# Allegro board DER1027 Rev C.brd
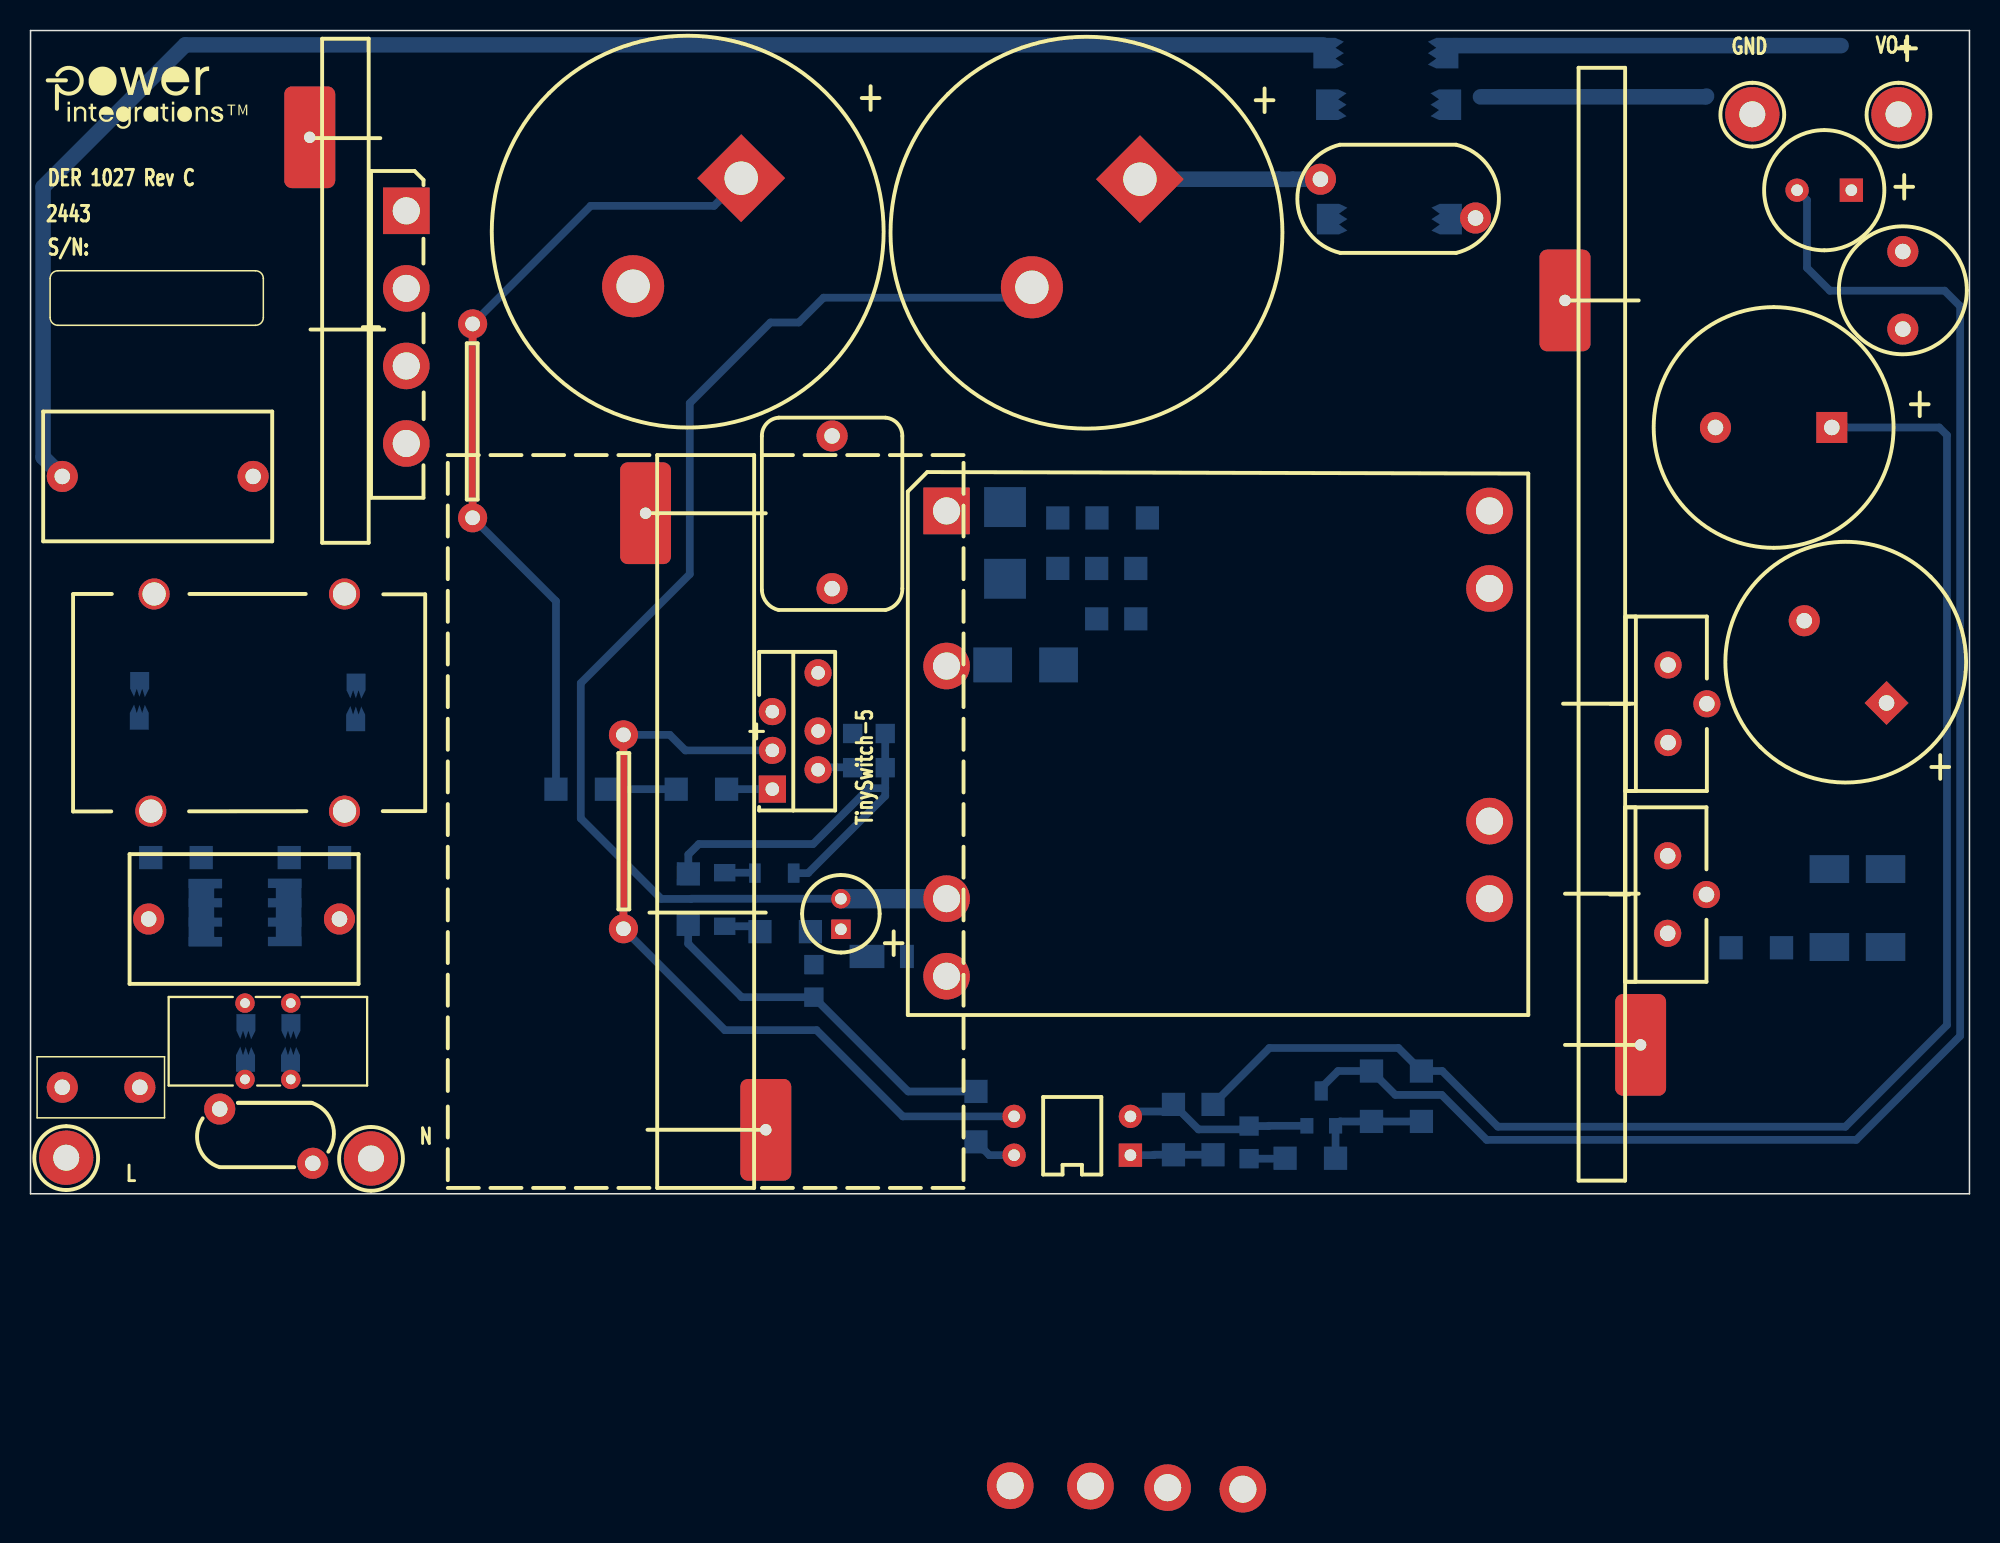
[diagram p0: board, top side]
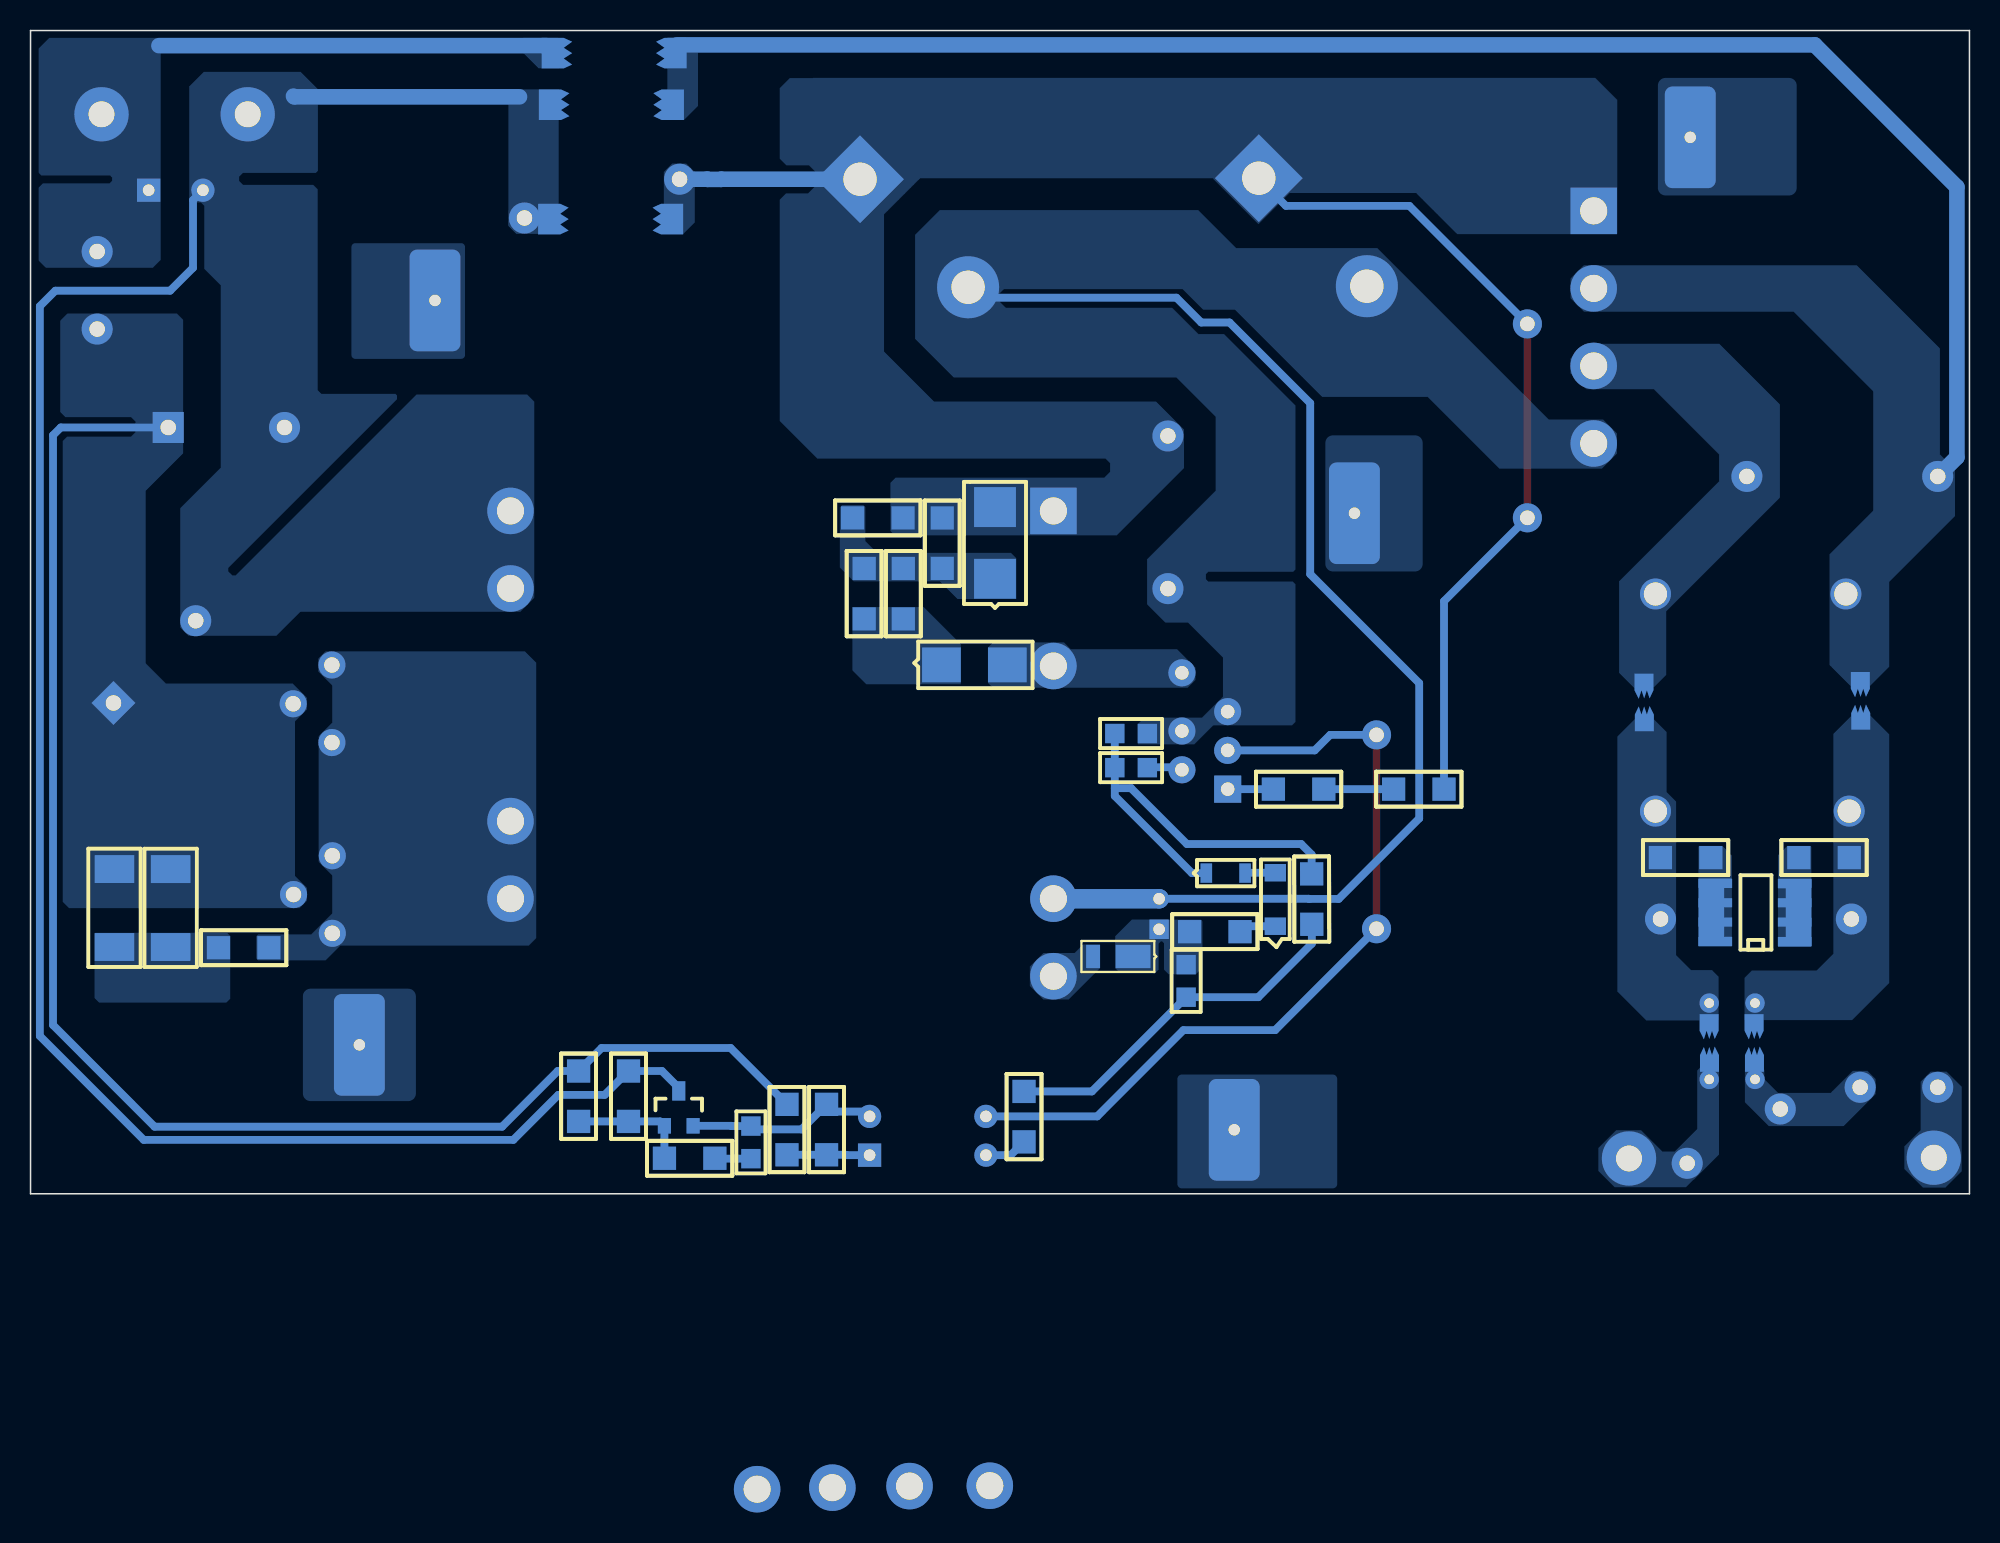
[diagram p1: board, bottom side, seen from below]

Outline 127 x 76.2 mm; copper layers: TOP, BOTTOM. Coordinates in mm from the lower left corner of the outline.
Outline path: 0,76.2 127,76.2 127,0 0,0 0,76.2

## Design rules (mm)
constraint set DEFAULT: min track width 0.508

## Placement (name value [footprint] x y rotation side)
BR1  GBU8K-BP  [PIDAXBRIDGEGBU8]  24.61 64.39 270 top
C1  330 nF  [PINP_XCAPRAD15X8P5X14HD040]  20.24 18 180 top
C2  270 uF  [PIPOLCAPCLYD985LS394086]  46.57 66.51 225 top
C3  1 uF  [PINPCAPRAD_12P6X9P2_LS10_D40]  52.5 49.64 270 top
C4  0.47 uF  [PISMC0805]  55.98 30.15 180 bottom
C5  1000 pF  [PISMC1206]  67.28 44.27 270 bottom
C7  47 uF  [PIPOLCAPCLYD200LS80030]  53.08 17.33 90 top
C8  470 pF  [PISMC1206]  111.39 16.12 0 bottom
C9  1800 uF  [PIPOLCAPCLYD630LS300040]  121.57 32.15 135 top
C10  1800 uF  [PIPOLCAPCLYD630LS300040]  117.98 50.2 180 top
C12  22 nF  [PISMC0805]  79.81 4.43 270 bottom
C14  150 uF  [PIPOLCAPCLYD320LS140030]  119.26 65.74 180 top
C15  330 nF  [PINP_XCAPRAD15X8P5X14HD040]  14.58 46.99 180 top
C16  270 uF  [PIPOLCAPCLYD985LS394086]  72.68 66.44 225 top
CY1  2.2 nF  [PINPYCAPRAD540X290LS400040]  84.49 66.46 0 top
D1  BAV21WS-7-F  [PISMSOD323]  49.99 21.01 180 bottom
D2  RS2MA-13-F  [PISMDO214AC12]  67.34 34.65 180 bottom
D3  DFLR1200-7  [PISMDDFLR120012]  54.76 15.54 180 bottom
D4  V20202C-M3/4W  [PIDVTO2203VF1]  107.26 32.1 90 top
D6  V20202C-M3/4W  [PIDVTO2203VF1]  107.23 19.6 90 top
D7  BZT52-C10J  [PI_SM_SOD-123_12]  45.47 17.53 90 bottom
F1  5 A  [PI_RST_MICROFUSE]  2.08 6.97 0 top
HS1  HEATSINK  DRW Custom TOP-JX IC DER-1026  [PI_HS_2P_DER-1026_TOP-JX_IC]  41.05 48.39 270 top
HS2  HEATSINK DRW Custom Diode Bridge DER1027  [PIHSDER1027DB]  22.15 42.64 90 top
HS3  HEATSINK DRW Custom SECDIODE DER-1027  [PI_HS_2P_DER-1027_SECDIODE]  104.44 0.86 90 top
JP1  J  [PI_JUMPER500]  28.96 44.28 90 top
JP2  J  [PI_JUMPER500]  38.84 30.06 270 top
L1  250 uH  [PI_TOROID_CMC13X6_5P8P_V]  15.55 9.99 0 top
L2  10 mH  [PI_TOROID_BALUN_1]  7.87 39.29 270 top
L3  1.5 uH  [PI_CHOKE_TOKO]  122.64 56.64 90 top
L4  80 ohm  [PISMR0805]  55.98 27.91 180 bottom
NOREF  -  []  0 76.2 0 top
NOREF#2  -  []  -228.6 -144.78 0 top
NOREF#3  -  []  57.66 -90.3 0 top
NOREF#4  -  []  1.02 74.32 0 top
NOREF#5  -  []  0 0 90 top
R1  1 M  [PISMR1206]  7.87 22.02 0 bottom
R2  1 M  [PISMR1206]  16.94 22.02 0 bottom
R5  6.34 k  [PISMR0805]  51.31 15.01 270 bottom
R7  4.02M  [PISMR1206]  34.42 26.5 0 bottom
R8  4.02M  [PISMR1206]  42.29 26.5 0 bottom
R12  47  [PISMR1206]  51.08 17.17 180 bottom
R13  20  [PISMR2010]  117.82 21.27 270 bottom
R15  2 k  [PISMR1206]  74.86 2.56 90 bottom
R16  1.0 k  [PISMR1206]  77.45 5.86 270 bottom
R17  20.0 k  [PISMR1206]  85.48 2.33 180 bottom
R18  191 k  [PISMR1206]  91.1 8.04 270 bottom
R19  10 k  [PISMR1206]  87.83 4.74 90 bottom
R21  20  [PISMR1206]  72.4 40.96 270 bottom
R22  20  [PISMR1206]  69.83 40.96 270 bottom
R23  0  [PISMR1206]  43.08 17.65 89.9 bottom
R24  0  [PISMR1206]  61.93 6.7 270 bottom
R25  1.00 M  [PISMR1206]  69.85 44.27 0 bottom
R26  20  [PISMR2010]  121.5 21.27 270 bottom
RV1  275 Vac  [PIDISC350X160LS210X140040]  12.39 5.55 0 top
SG1  5.5mm gap  [PI_SPARK_GAP_5P5MM]  89 63.85 0 bottom
SG2  5.5mm gap  [PI_SPARK_GAP_5P5MM]  88.95 71.34 0 bottom
SG3  5.5mm gap  [PI_SPARK_GAP_5P5MM]  88.78 74.72 0 bottom
T1  PQ35/35  [PI_BOBBIN_BPQ35_35_12P]  60 44.73 0 top
TP1  L (BLK)  [PITPKEYSTONE125X125]  2.34 2.36 0 top
TP2  N (WHT)  [PITPKEYSTONE125X125]  22.3 2.31 0 top
TP3  VO+ (RED)  [PITPKEYSTONE125X125]  122.35 70.71 0 top
TP4  GND (BLK)  [PITPKEYSTONE125X125]  112.78 70.71 0 top
U1  CAP200DG  [PI_IC_SMD_SO8_CAPZERO]  11.45 16.53 90 bottom
U2  TNY5077E  [PIICESIP76TH]  48.59 26.5 90 top
U3  LTV817D  [PI_DIP4]  72.04 2.53 90 top
U4  LMV431AIMF  [PISMSOT23132]  83.6 4.45 180 bottom
VR2  SMBJ170A  [PISMDO214AA12]  63.83 40.28 90 bottom

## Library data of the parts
BR1 = DISCRETE BRIDGE_+~~-: alternate symbols: (pidaxbridgegbu8_horz)
C1 C15 = CAP NP: alternate symbols: (pinp_xcaprad15x8p5x14Hd040H); room: 1
C2 C16 = CAP POL
C3 = CAP NP: alternate symbols: (pinpcaprad_12p6x9p2_ls10_d400H)
C4 C12 = CAP NP: alternate symbols: (Unisem_RMCF0805UL)
C5 = CAP NP: tolerance: 10
C7 = CAP POL: alternate symbols: (pipolcapclyd200ls80030h); tolerance: 20
C8 = CAP NP: alternate symbols: (pismc1206_1); tolerance: 10
C9 C10 = CAP POL: alternate symbols: (pipolcapclyd630ls3000401000h)
C14 = CAP POL: alternate symbols: (pipolcapclyd320ls140030430h); tolerance: 20
CY1 = CAP NP
D1 = DIODE: alternate symbols: (SOD323_UL_IPC,pismsod323_1)
D2 D3 = DIODE
D4 D6 = DS_DUAL_CK_AKA: alternate symbols: (pidvto2203,pidvto2203h)
D7 = ZENER_DIODE
F1 = FUSE: alternate symbols: (pirstmicrofusehoz); room: 1
HS1 = hs_2P_DER-1026_TOP-JXIC
HS2 = hs_1P_DER1027DB
HS3 = hs_2P_DER-1027_SECDIODE
JP1 JP2 = JUMPER_2
L1 = TORRID 4P_12_34: room: 1
L2 = TORRID 4P_12_34
L3 = INDUCTOR: alternate symbols: (pi_choke_toko_h); tolerance: 0.2
L4 = INDUCTOR_BEAD_2
R1 R2 R12 R13 R15-R19 R21-R26 = R
R5 = R: alternate symbols: (Unisem_RMCF0805UL)
R7 R8 = R: alternate symbols: (pismr1206_1)
RV1 = VARISTOR: alternate symbols: (pi_disc_354x220_ls220x10_040_h); room: 1
SG1-SG3 = SPARK_GAP
T1 = BPQ35/35_12P/GENERIC
TP1-TP4 = TESTPOINT
U1 = CAPZero: room: 1
U2 = TinySwitch-5E
U3 = OPTO_A_B
U4 = TL431/SOT-23_RCA
VR2 = DIODE_ZENER

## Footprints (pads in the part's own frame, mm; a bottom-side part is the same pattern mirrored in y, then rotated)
PI_BOBBIN_BPQ35_35_12P
  rect 3.048x3.048 hole 1.778: 1(0,0)
  round 3.048 hole 1.778: 2(19.406,-64.084) 3(0,-10.16) 4(4.166,-63.856) 5(0,-25.4) 6(0,-30.48) 7(9.423,-63.881) 8(35.56,-25.4) 9(35.56,-20.32) 10(14.478,-63.983) 11(35.56,-5.08) 12(35.56,0)
PI_CHOKE_TOKO
  round 2.032 hole 1.016: 1(0,0) 2(5.08,0)
PI_DIP4
  rect 1.524x1.524 hole 0.762: 1(0,0)
  round 1.524 hole 0.762: 2(2.54,0) 3(2.54,7.62) 4(0,7.62)
PI_HS_2P_DER-1026_TOP-JX_IC
  rrect 6.66x3.333 hole 0.75: 1(3.81,-0.762) 2(44.199,7.112)
PI_HS_2P_DER-1027_SECDIODE
  rrect 6.66x3.333 hole 0.75: 1(8.893,-1.016) 2(57.658,3.937)
PI_IC_SMD_SO8_CAPZERO
  rect 0.599x2.2 smd: 1(0,0) 2(1.27,0) 3(2.54,0) 4(3.81,0) 5(3.81,5.199) 6(2.54,5.199) 7(1.27,5.199) 8(0,5.199)
PI_JUMPER500
  round 1.905 hole 0.965: 1(0,0) 2(12.7,0)
PI_RST_MICROFUSE
  round 2.032 hole 1.016: 1(0,0) 2(5.08,0)
PI_SM_SOD-123_12
  rect 1.143x1.397 smd: 1(0,0) 2(3.505,0)
PI_SPARK_GAP_5P5MM
  custom 0.5x0.5 smd: 1(-3.75,0) 2(3.75,0)
PI_TOROID_BALUN_1
  round 2.032 hole 1.524: 1(14.224,0.013) 2(0,0.229) 3(14.224,12.7) 4(0,12.7)
PI_TOROID_CMC13X6_5P8P_V
  round 1.27 hole 0.635: 1(1.5,-2.5) 2(1.5,2.5) 3(-1.5,-2.5) 4(-1.5,2.5)
PIDAXBRIDGEGBU8
  rect 3.048x3.048 hole 1.778: 1(0,0)
  round 3.048 hole 1.778: 2(5.08,0) 3(10.16,0) 4(15.24,0)
PIDISC350X160LS210X140040
  round 2.032 hole 1.016: 1(0,0) 2(6.096,-3.556)
PIDVTO2203VF1
  round 1.778 hole 1.016: 1(-2.54,0) 2(0,-2.54) 3(2.54,0)
PIHSDER1027DB
  rrect 6.66x3.333 hole 0.75: 1(26.561,3.861)
PIICESIP76TH
  rect 1.778x1.778 hole 0.889: 1(0,0)
  round 1.778 hole 0.889: 2(1.27,-2.997) 3(2.54,0) 4(3.81,-2.997) 5(5.08,0) 7(7.62,-2.997)
PINP_XCAPRAD15X8P5X14HD040
  round 2.032 hole 1.016: 1(0,0) 2(12.499,0)
PINPCAPRAD_12P6X9P2_LS10_D40
  round 2.032 hole 1.016: 1(0,0) 2(10,0)
PINPYCAPRAD540X290LS400040
  round 2.032 hole 1.016: 1(0,0) 2(10.16,-2.54)
PIPOLCAPCLYD200LS80030
  rect 1.27x1.27 hole 0.762: 1(0,0)
  round 1.27 hole 0.762: 2(2,0)
PIPOLCAPCLYD320LS140030
  rect 1.524x1.524 hole 0.762: 1(0,0)
  round 1.524 hole 0.762: 2(3.556,0)
PIPOLCAPCLYD630LS300040
  rect 2.032x2.032 hole 1.016: 1(0,0)
  round 2.032 hole 1.016: 2(7.62,0)
PIPOLCAPCLYD985LS394086
  rect 4.064x4.064 hole 2.184: 1(0,-0.025)
  round 4.064 hole 2.184: 2(10.008,-0.025)
PISMC0805
  rect 1.27x1.27 smd: 1(0,0) 2(2.134,0)
PISMC1206
  rect 1.524x1.524 smd: 1(0,0) 2(3.302,0)
PISMDDFLR120012
  rect 2.286x1.524 smd: 1(-0.025,0)
  rect 0.914x1.524 smd: 2(-2.642,0)
PISMDO214AA12
  rect 2.616x2.743 smd: 1(0,0) 2(4.699,0)
PISMDO214AC12
  rect 2.54x2.286 smd: 1(0,0) 2(4.318,0)
PISMR0805
  rect 1.27x1.27 smd: 1(0,0) 2(2.134,0)
PISMR1206
  rect 1.524x1.524 smd: 1(0,0) 2(3.302,0)
PISMR2010
  rect 1.829x2.591 smd: 1(0,0) 2(5.105,0)
PISMSOD323
  rect 0.762x1.27 smd: 1(0,0) 2(2.54,0)
PISMSOT23132
  rect 0.864x1.016 smd: 1(-1.88,0) 2(0,0)
  rect 0.864x1.27 smd: 3(-0.94,2.286)
PITPKEYSTONE125X125
  round 3.556 hole 1.702: 1(0,0)

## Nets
BR: BR1.2 C15.2 L2.2 SG2.1 SG3.1
N1180530: C9.2 C10.2 C14.2 CY1.2 R19.2 SG1.2 SG2.2 T1.11 T1.12 TP4.1 U4.3
N1180572: C8.1 D4.1 D4.3 D6.1 D6.3 T1.8 T1.9
N1180580: C8.2 R13.2 R26.2
N1180772: C9.1 C10.1 D4.2(CATHODE) D6.2(CATHODE) L3.1 R13.1 R16.1 R18.1 R26.1
N1180800: C14.1 L3.2 SG3.2 TP3.1
N1180998: BR1.4 C2.2 C3.2 C4.2 C7.2 C16.2 T1.5 U2.4 U2.5
N1181144: R7.2 R8.1
N1181148: D2.2 T1.3 U2.7
N1181266: C7.1 D3.1 R5.1 R12.1
N1181270: R15.1 R16.2 U3.1
N1181336: R17.1 R18.2 R19.1 U4.1(VREF)
N1181354: R8.2 U2.1
N1181442: C12.1 R15.2 U3.2 U4.2
N1193924: D1.2 D7.2
N1193928: D7.1(CATHODE) R12.2
N11509583: C1.2 L1.4 L2.1 R1.1
N11509663: R1.2 U1.1 U1.2 U1.3 U1.4
N11509667: R2.1 U1.5 U1.6 U1.7 U1.8(NC8)
N11509705: C1.1 L1.2 L2.3 R2.2
N11509765: F1.2 L1.3 RV1.1
N11509809: L1.1 RV1.2 TP2.1
N11514098: C12.2 R17.2
N11558446: BR1.3(AC2) C15.1 L2.4
N11565135: C5.2 R21.1 R22.1 R25.2 VR2.1
N11566250: F1.1 TP1.1
N11596495: D2.1 R21.2 R22.2
N11618490: D3.2 T1.6
N12576026: C4.1 D1.1 L4.1 R23.2
N12603395: BR1.1 C2.1 C3.1 C5.1 C16.1 CY1.1 JP1.1 JP1.2 R7.1 R25.1 SG1.1 T1.1 VR2.2
N12603576: JP2.1 JP2.2 U2.3 U3.3(E)
N12614295: R5.2 R23.1 R24.1
N12614386: R24.2 U3.4
N12619931: HS1.2
N12619939: HS1.1
N12620029: HS2.1
N12620119: HS3.2
N12620127: HS3.1
N12646059: L4.2 U2.2

Pads without a net: T1 2 4 7 10

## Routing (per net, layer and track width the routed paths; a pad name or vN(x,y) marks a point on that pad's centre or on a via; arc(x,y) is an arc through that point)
BR: length 107.2
  BOTTOM w1.016: 84.67,75.26 10.13,75.26 0.82,65.95 0.82,48.25 C15.2
N1180530: length 126.3
  BOTTOM w0.508: C14.2 116.36,65.09 116.36,60.66 117.86,59.16 125.37,59.16 126.39,58.14 126.39,10.34 119.58,3.53 95.38,3.53 92.43,6.48 89.4,6.48 R19.2 85.64,8.04 84.54,6.94 U4.3
  BOTTOM w1.016: 94.97,71.86 109.73,71.86 109.78,71.91
N1180772: length 100.9
  BOTTOM w0.508: C10.1 125.02,50.2 125.53,49.69 125.53,11.05 118.87,4.39 96.11,4.39 92.47,8.04 R18.1 89.59,9.55 81.15,9.55 R16.1
N1180800: length 25.4
  BOTTOM w1.016: 93.18,75.21 118.59,75.21
N1180998: length 83.1
  BOTTOM w0.508: C7.2 43.27,19.33 43.26,19.31 41.32,19.31 36.04,24.59 36.04,33.45 43.18,40.59 43.18,51.79 48.46,57.07 50.32,57.07 51.94,58.7 64.55,58.7 64.73,58.52 C16.2 64.83,58.62
  BOTTOM w1.27: C7.2 60,19.33 T1.5
N1181144: length 4.6
  BOTTOM w0.508: R7.2 R8.1
N1181270: length 5.4
  BOTTOM w0.508: R16.2 R15.1 73.59,2.56 73.57,2.53 U3.1
N1181336: length 7.9
  BOTTOM w0.508: R18.2 R19.1 85.77,4.74 U4.1 85.48,2.33 R17.1
N1181354: length 3
  BOTTOM w0.508: R8.2 U2.1
N1181442: length 12.7
  BOTTOM w0.508: U3.2 72.36,5.38 74.39,5.38 R15.2 76.5,4.22 79.6,4.22 C12.1 81.08,4.43 81.1,4.45 U4.2
N1193924: length 2
  BOTTOM w0.508: D1.2 47.42,21.03 D7.2
N1193928: length 2.5
  BOTTOM w0.508: R12.2 47.42,17.53 D7.1
N11514098: length 2.4
  BOTTOM w0.508: R17.2 82.15,2.3 C12.2
N12576026: length 28.1
  BOTTOM w0.508: D1.1 50.93,21.01 55.98,26.06 55.98,26.57 ; 55.98,26.57 L4.1 C4.1 ; 55.98,26.57 54.91,26.57 51.26,22.91 43.77,22.91 43.09,22.23 43.09,20.95
N12603395: length 66.1
  TOP w0.508: JP1.2 JP1.1
  BOTTOM w0.508: JP1.2 36.69,64.71 44.77,64.71 46.57,66.51 ; JP1.1 34.42,38.82 R7.1
  BOTTOM w1.016: CY1.1 82.67,66.46 82.66,66.45 81.77,66.45 81.76,66.46 C16.1
N12603576: length 53.5
  TOP w0.508: JP2.1 JP2.2
  BOTTOM w0.508: U3.3 57.13,5.07 51.49,10.72 45.48,10.72 JP2.2 ; U2.3 42.89,29.04 41.87,30.06 JP2.1
N12614295: length 24.1
  BOTTOM w0.508: R23.1 43.08,16.38 46.58,12.88 R5.2 57.48,6.7 R24.1
N12614386: length 2.9
  BOTTOM w0.508: U3.4 62.8,2.53 R24.2
N12646059: length 2.3
  BOTTOM w0.508: U2.2 51.75,27.94 53.82,27.94 L4.2

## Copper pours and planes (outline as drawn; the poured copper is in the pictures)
BR on BOTTOM (solid shape): 7.77,33.09 7.49,32.53 7.31,33.09 7.13,32.55 6.96,33.09 6.78,32.55 6.53,33.09 6.53,34.18 7.77,34.18
BR on BOTTOM: 84.19,70.35 85.29,70.35 85.29,75.75 83.85,75.75 83.28,75.18 83.28,71.26
BR on BOTTOM: 9.17,41.88 6.31,44.75 6.31,52.57 11.52,57.78 25.25,57.78 26.13,58.66 26.13,59.95 25.26,60.82 7.39,60.82 1.94,55.38 1.94,48.44 0.95,47.45 0.95,44.39 5.26,40.08 5.26,34.52 6.55,33.22 7.75,33.22 9.17,34.65
N1180530 on BOTTOM: 92.91,64.89 92.74,64.72 92.74,62.97 92.82,62.89 95.17,62.89 95.71,63.42 95.71,63.7 95.7,63.71 95.7,64.4 95.2,64.89
N1180530 on BOTTOM: 92.41,72.35 92.41,62.89 95.18,62.89 95.7,63.41 95.7,71.85 95.21,72.35
N1180530 on BOTTOM: 109.32,38.12 110.9,36.55 116.65,36.55 117.2,37.09 117.2,44.91 114.54,47.56 114.54,59.51 115.62,60.59 115.62,64.72 115.84,64.94 116.5,64.94 116.61,65.05 116.61,72.56 116.58,72.56 115.65,73.49 109.31,73.49 108.18,72.36 108.18,67.01 108.31,66.88 113.1,66.88 113.1,66.86 113.34,66.62 113.34,66.35 113.08,66.09 108.48,66.09 108.19,65.8 108.19,52.64 107.95,52.4 103.1,52.4 103,52.3 103,52.04 114.05,40.99 114.05,40.77 113.91,40.63 113.78,40.51 113.56,40.51 101.71,52.36 94.48,52.36 94.01,51.89 94.01,39.12 94.01,39.11 94.01,39.04 94.92,38.12
N1180572 on BOTTOM: 107.24,18.36 107.24,20.85 108.13,21.74 108.13,29.98 107.24,30.86 107.24,33.3 108.15,34.21 108.15,35.05 107.67,35.53 94.62,35.53 93.88,34.79 93.88,16.74 94.37,16.26 106.71,16.26 107.67,15.29 112.09,15.29 112.22,15.42 112.22,16.87 112.09,16.99 108.61,16.99
N1180580 on BOTTOM: 122.81,17.04 122.81,12.83 122.5,12.52 114.17,12.52 113.92,12.78 113.92,16.89 114.12,17.09 122.76,17.09
N1180772 on BOTTOM: 109.68,30.95 108.89,31.73 108.89,32.49 109.83,33.43 118.14,33.43 119.46,34.75 119.46,46.05 117.01,48.5 117.01,57.26 117.41,57.67 124.58,57.67 125.06,57.19 125.06,51.22 124.71,50.88 120.42,50.88 120.13,50.58 120.13,49.89 120.42,49.6 124.6,49.6 124.89,49.31 124.89,19.13 124.48,18.71 109.38,18.71 108.89,19.2 108.89,20.03 109.68,20.82
N1180800 on BOTTOM: 126.47,75.03 126.47,66.88 126.29,66.7 121.79,66.7 121.66,66.57 121.66,66.36 121.82,66.19 126.19,66.19 126.47,65.91 126.47,61.13 125.99,60.66 118.99,60.66 118.47,61.17 118.47,75.57 118.62,75.72 125.77,75.72
N1180800 on BOTTOM: 92.43,75.73 92.43,73.73 93.72,73.73 94.7,74.71 94.7,75.73 94.7,75.73 92.43,75.73
N1180998 on BOTTOM: 44.37,30.68 44.15,30.91 44.15,39.93 44.32,40.11 49.86,40.11 50.01,40.26 50.01,40.59 49.86,40.74 44.3,40.74 44.15,40.89 44.15,51.64 48.82,56.31 50.5,56.31 52.22,58.04 63.12,58.04 63.55,58.47 63.55,58.95 63.25,59.26 51.54,59.26 50.19,57.91 48.11,57.91 42.39,52.2 35.48,52.2 30.78,47.5 24.08,47.5 23.09,48.49 23.09,49.81 24,50.72 27.56,50.72 38.79,61.95 48.03,61.95 50.52,64.44 67.44,64.44 69.06,62.81 69.06,56.01 66.52,53.47 51.94,53.47 49.38,50.9 49.38,46.05 53.88,41.55 53.87,41.53 53.87,38.61 52.67,37.41 51.18,37.41 48.9,35.13 48.9,32.56 50.27,31.19 54.05,31.19 54.47,30.77 54.47,29.44 50.77,29.44 49.53,30.68
N1181148 on BOTTOM: 51.21,33.15 63.97,33.15 64.29,33.46 64.29,35.79 63.96,36.12 59.31,36.12 58.86,35.67 51.9,35.67 50.7,34.47 50.7,33.66
N1181266 on BOTTOM: 53.67,17.96 53.68,17.97 54.86,17.97 55.96,16.87 55.96,14.78 55.7,14.53 53.26,14.53 53.11,14.68 53.11,16.38 52.96,16.54 52.88,16.54 52.76,16.41 52.76,14.68 52.45,14.38 50.67,14.38 50.24,14.81 50.24,17.86 50.34,17.96
N11509583 on BOTTOM (solid shape): 6.96,31.49 7.13,32.03 7.31,31.49 7.49,32.03 7.74,31.49 7.74,30.4 6.5,30.4 6.5,31.49 6.78,32.05
N11509583 on BOTTOM (solid shape): 14.73,10.68 14.45,10.12 14.27,10.68 14.09,10.14 13.92,10.68 13.74,10.14 13.48,10.68 13.48,11.77 14.73,11.77
N11509583 on BOTTOM: 14.73,11.38 14.73,14.15 14.25,14.63 10.01,14.63 8.92,15.72 8.92,30.12 7.72,31.32 6.48,31.32 5.26,30.1 5.26,13.8 7.68,11.38
N11509663 on BOTTOM (solid shape): 12.54,20.01 12.03,20.01 12.03,16.8 12.54,16.8 12.54,16.2 10.36,16.2 10.36,20.61 12.54,20.61
N11509663 on BOTTOM: 10.36,16.22 12.54,16.22 12.54,22.18 11.94,22.78 10.41,22.78 10.36,22.73
N11509667 on BOTTOM (solid shape): 17.75,16.22 15.56,16.22 15.56,16.83 16.07,16.83 16.07,20.03 15.56,20.03 15.56,20.64 17.75,20.64
N11509667 on BOTTOM: 17.75,17.57 17.75,17.57 17.75,16.22 15.56,16.22 15.56,22.17 16.18,22.78 17.7,22.78 17.75,22.73
N11509705 on BOTTOM (solid shape): 17.68,10.68 17.4,10.12 17.22,10.68 17.04,10.14 16.86,10.68 16.69,10.14 16.43,10.68 16.43,11.77 17.68,11.77
N11509705 on BOTTOM (solid shape): 21.13,31.39 21.31,31.93 21.49,31.39 21.66,31.93 21.92,31.39 21.92,30.3 20.67,30.3 20.67,31.39 20.95,31.95
N11509705 on BOTTOM: 16.43,11.35 16.43,14.22 16.87,14.66 18.24,14.66 19.22,15.63 19.22,25.69 19.84,26.31 19.84,30.25 20.7,31.11 21.89,31.11 23.06,29.95 23.06,13.25 21.17,11.35
N11509765 on BOTTOM (solid shape): 13.92,9.08 14.09,9.62 14.27,9.08 14.45,9.62 14.7,9.08 14.7,7.99 13.46,7.99 13.46,9.08 13.74,9.64
N11509765 on BOTTOM: 14.71,8.13 14.49,8.35 13.67,8.35 13.44,8.12 13.44,7.51 12.53,6.6 9.09,6.6 7.65,8.05 6.68,8.05 6.15,7.52 6.15,6.53 8.24,4.43 13.15,4.43 14.71,5.99
N11509809 on BOTTOM (solid shape): 16.86,9.08 17.04,9.62 17.22,9.08 17.4,9.62 17.65,9.08 17.65,7.99 16.41,7.99 16.41,9.08 16.69,9.64
N11509809 on BOTTOM: 16.41,8.03 16.41,2.57 18.06,0.91 18.08,0.91 18.57,0.43 23.27,0.43 23.27,0.46 24.31,1.5 24.31,3 23.14,4.17 21.51,4.17 20.12,2.77 19.3,2.77 17.83,4.24 17.83,8.08 17.6,8.31 16.69,8.31
N11558446 on BOTTOM (solid shape): 21.94,32.98 21.66,32.43 21.49,32.98 21.31,32.45 21.13,32.98 20.95,32.45 20.7,32.98 20.7,34.08 21.94,34.08
N11558446 on BOTTOM: 16.4,46.67 16.4,48.43 20.68,52.7 25.1,52.7 26.14,53.75 26.14,54.71 25.17,55.68 16.38,55.68 12.42,51.71 12.42,45.59 19.86,38.15 19.86,33.99 20.7,33.15 21.97,33.15 22.95,34.12 22.95,40.12
N11565135 on BOTTOM: 62.43,38.96 66.28,38.96 67.44,40.12 73.08,40.12 73.99,41.03 73.99,44.97 73.85,45.11 72.44,45.11 72.32,44.98 72.32,42.75 71.55,41.98 62.78,41.98 62.43,41.63
N11566250 on BOTTOM: 1.5,8 0.51,7.01 0.51,1.48 1.57,0.41 3.05,0.41 4.26,1.62 4.26,3.1 3.2,4.17 3.2,7.34 2.54,8
N11596495 on BOTTOM: 73.16,38.42 73.16,38.43 68.49,38.43 66.07,36 66.07,33.37 70.51,33.37 70.51,33.38 72.26,33.38 73.16,34.28
N11618490 on BOTTOM: 58.61,15.77 60.66,15.77 61.54,14.88 61.54,13.61 60.66,12.73 59,12.73 56.95,14.78 56.95,16.31 56.97,16.33 58.05,16.33
N12603395 on BOTTOM: 55.85,43.13 51.45,47.54 51.45,50.06 53.28,51.9 67.82,51.9 71.09,55.17 71.09,64.16 68.73,66.52 49.53,66.52 49.53,66.47 46.58,63.53 46.56,63.53 44.53,65.56 36.25,65.56 33.55,62.87 23.09,62.87 23.06,62.89 23.06,65.94 23.07,65.94 23.07,71.66 24.51,73.1 75.74,73.1 75.76,73.09 77.27,73.09 77.93,72.43 77.93,67.81 77.48,67.36 76.01,67.36 75.51,66.87 75.51,66.1 76.08,65.53 77.52,65.53 77.93,65.12 77.93,50.62 75.46,48.16 56.59,48.16 56.29,47.85 56.29,47.29 56.67,46.91 70.34,46.91 70.68,46.57 70.68,43.42 70.39,43.13
N12603395 on BOTTOM: 84.05,67.49 83.49,66.93 83.49,63.63 84.24,62.88 85.29,62.88 85.52,63.11 85.52,66.94 84.97,67.49
N12619931 on BOTTOM (solid shape): 49.48,1.17 46.94,1.17 46.94,7.27 49.48,7.27
N12619931 on BOTTOM: 41.41,0.65 41.5,0.44 41.71,0.35 51.58,0.35 51.79,0.44 51.88,0.65 51.88,7.51 51.79,7.72 51.58,7.81 41.71,7.81 41.5,7.72 41.41,7.51
N12619939 on BOTTOM (solid shape): 41.55,41.53 39.01,41.53 39.01,47.63 41.55,47.63
N12619939 on BOTTOM: 35.81,41.27 35.96,40.91 36.31,40.77 41.69,40.77 42.04,40.91 42.19,41.27 42.19,49.18 42.04,49.54 41.69,49.68 36.31,49.68 35.96,49.54 35.81,49.18
N12620029 on BOTTOM (solid shape): 19.51,66.13 16.97,66.13 16.97,72.22 19.51,72.22
N12620029 on BOTTOM: 11.32,65.9 11.46,65.54 11.82,65.4 19.91,65.4 20.26,65.54 20.41,65.9 20.41,72.59 20.26,72.95 19.91,73.09 11.82,73.09 11.46,72.95 11.32,72.59
N12620119 on BOTTOM (solid shape): 101.73,55.44 99.19,55.44 99.19,61.54 101.73,61.54
N12620119 on BOTTOM: 98.54,54.95 98.62,54.77 98.8,54.69 105.73,54.69 105.91,54.77 105.98,54.95 105.98,62.02 105.91,62.2 105.73,62.27 98.8,62.27 98.62,62.2 98.54,62.02
N12620127 on BOTTOM (solid shape): 106.73,6.7 104.19,6.7 104.19,12.8 106.73,12.8
N12620127 on BOTTOM: 101.76,6.57 101.91,6.22 102.26,6.07 108.66,6.07 109.01,6.22 109.16,6.57 109.16,12.93 109.01,13.29 108.66,13.43 102.26,13.43 101.91,13.29 101.76,12.93

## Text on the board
Ref Des/Silkscreen Top: 2443 | DER 1027 Rev C | S/N: | L | N | GND | VO+ | TinySwitch-5 | +
User.5: PLATED | SLOT
User.8: FIGURE | FINISHED_SIZE | 25.0 | 29.53 | 30.0 | 35.0 | 38.0 | 40.0 | 60.0 | 67.0 | 70.0 | 80.0 | DRILL CHART: TOP to BOTTOM | ALL UNITS ARE IN MILS | TOLERANCE_DRILL | +3.0/-3.0 | PLATED | QTY | 4 | 5 | 8 | 6 | 24 | 16 | 79 | TOTAL HOLES:
